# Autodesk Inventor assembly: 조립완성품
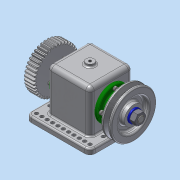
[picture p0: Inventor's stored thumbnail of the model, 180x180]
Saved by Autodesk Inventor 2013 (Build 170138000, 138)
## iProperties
Created: 2018-11
Part Number: 조립완성품
Document SubType Name: Assembly
Designer: dgall
Author: dgall
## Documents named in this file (13)
- C:\Users\dgall\Desktop\481107V1031\조립완성품.iam
- C:\Users\dgall\Desktop\481107V1031\본체.ipt
- C:\Users\dgall\Desktop\481107V1031\축.ipt
- C:\Users\dgall\Desktop\481107V1031\베어링 6203.ipt
- C:\Users\dgall\Desktop\481107V1031\커버.ipt
- C:\Users\dgall\Desktop\481107V1031\오일 실 26 38 8.ipt
- C:\Users\dgall\Desktop\481107V1031\부시.ipt
- C:\Users\dgall\Desktop\481107V1031\키 5x5x12.ipt
- C:\Users\dgall\Desktop\481107V1031\스퍼기어.ipt
- C:\Users\dgall\Desktop\481107V1031\V벨트풀리.ipt
- C:\Users\dgall\Desktop\481107V1031\와셔 12x24.ipt
- C:\Users\dgall\Desktop\481107V1031\너트 M12x1.25.ipt
- C:\Users\dgall\Desktop\481107V1031\볼트 M4.ipt
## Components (1 placed, 1 different names)
1. V벨트풀리:1 — 각도:4
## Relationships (1: Angle 1)
- 각도:4 [Angle]: V벨트풀리:1
